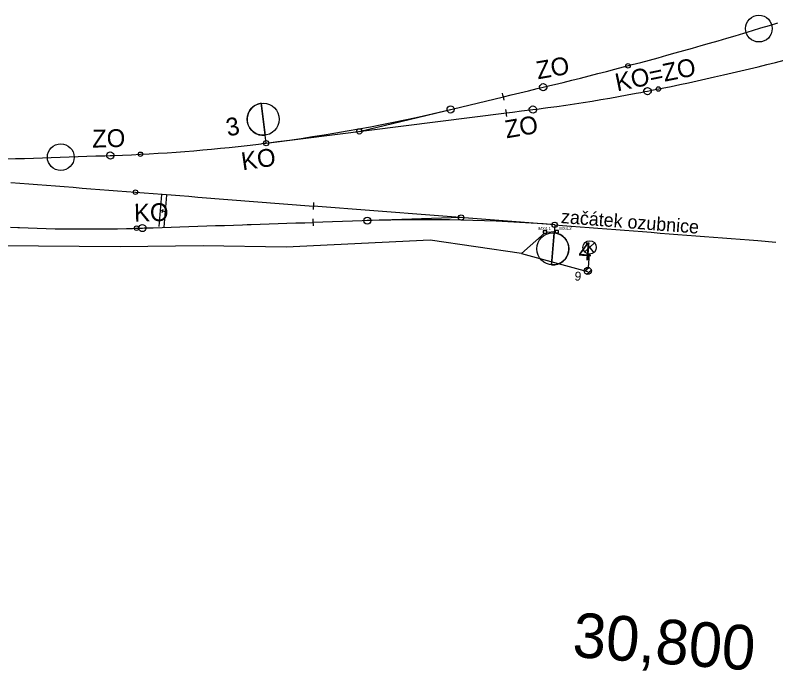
# Model space of a CAD drawing. Extents: x -669628 to -669207, y -977198 to -977075.
# Drawn here: x -669433.2 to -669347.9, y -977198.3 to -977124.9 of the extents above; entities that cross this region are included whole.
import ezdxf

# ---------------------------------------------------------------- set-up
doc = ezdxf.new("R2010")
doc.units = 0
for name, color, linetype in [('KOL_námezníky', 7, 'Continuous'), ('Navazující stavba', 7, 'Continuous'), ('SO 01-86-01', 7, 'Continuous'), ('SO 11-10-01', 7, 'Continuous')]:
    doc.layers.add(name, color=color, linetype=linetype)

# ---------------------------------------------------------------- blocks, each defined once
blk = doc.blocks.new('POINT_DISPLAY')
blk.add_line((0, 0), (0, 0))
blk = doc.blocks.new('Z3.50')
at = {"layer": 'KOL_námezníky'}
for p, q in [((-27.7, 181.3), (-26.5, -174.8)), ((33.2, -174.7), (31.9, 181.4))]:
    blk.add_line(p, q, dxfattribs=at)

msp = doc.modelspace()

# ---------------------------------------------------------------- linework, layer by layer
at = {"layer": 'Navazující stavba'}
msp.add_lwpolyline([(-669372.712, -977148.358), (-669371.856, -977148.424), (-669370.859, -977148.502), (-669369.862, -977148.579), (-669368.865, -977148.657), (-669367.868, -977148.735), (-669366.871, -977148.812), (-669365.874, -977148.89), (-669364.877, -977148.967), (-669363.88, -977149.045), (-669362.883, -977149.123), (-669361.886, -977149.2), (-669360.889, -977149.278), (-669359.892, -977149.355), (-669358.895, -977149.433), (-669357.898, -977149.511), (-669356.901, -977149.588), (-669355.905, -977149.666), (-669354.908, -977149.744), (-669353.911, -977149.821), (-669352.914, -977149.899), (-669351.917, -977149.976), (-669350.92, -977150.054), (-669349.923, -977150.132), (-669347.929, -977150.287)], dxfattribs=at)
at = {"layer": 'SO 01-86-01'}
for p, q in [((-669373.608, -977149.016), (-669373.987, -977149.016)), ((-669373.987, -977149.016), (-669373.987, -977149.292)), ((-669373.608, -977149.292), (-669373.608, -977149.016)), ((-669373.608, -977149.19), (-669372.647, -977149.113)), ((-669372.268, -977148.976), (-669372.647, -977148.976)), ((-669372.647, -977148.976), (-669372.647, -977149.251)), ((-669372.268, -977149.251), (-669372.268, -977148.976)), ((-669376.446, -977151.556), (-669373.862, -977149.292)), ((-669373.987, -977149.292), (-669373.608, -977149.292)), ((-669372.647, -977149.251), (-669372.268, -977149.251)), ((-669421.416, -977150.84), (-669436.037, -977150.686)), ((-669412.108, -977150.726), (-669421.416, -977150.84)), ((-669402.797, -977150.85), (-669412.108, -977150.726)), ((-669386.675, -977150.085), (-669402.797, -977150.85)), ((-669376.446, -977151.556), (-669386.675, -977150.085)), ((-669369.341, -977151.401), (-669368.256, -977150.369)), ((-669369.255, -977150.292), (-669368.343, -977151.479)), ((-669376.446, -977151.556), (-669369.045, -977153.593)), ((-669368.857, -977151.631), (-669368.973, -977153.127)), ((-669369.398, -977153.575), (-669368.894, -977153.144)), ((-669369.154, -977153.892), (-669368.617, -977153.432))]:
    msp.add_line(p, q, dxfattribs=at)
for centre, radius in [((-669368.799, -977150.885), 0.749), ((-669369.004, -977153.526), 0.4)]:
    msp.add_circle(centre, radius, dxfattribs=at)
at = {"layer": 'SO 11-10-01'}
for p, q in [((-669349.596, -977126.298), (-669348.639, -977126.006)), ((-669348.639, -977126.006), (-669347.684, -977125.712)), ((-669352.469, -977127.161), (-669351.511, -977126.876)), ((-669351.511, -977126.876), (-669350.553, -977126.588)), ((-669350.553, -977126.588), (-669349.596, -977126.298)), ((-669355.348, -977128.003), (-669354.388, -977127.725)), ((-669354.388, -977127.725), (-669353.428, -977127.444)), ((-669353.428, -977127.444), (-669352.469, -977127.161)), ((-669358.234, -977128.825), (-669357.271, -977128.553)), ((-669357.271, -977128.553), (-669356.31, -977128.279)), ((-669356.31, -977128.279), (-669355.348, -977128.003)), ((-669361.125, -977129.627), (-669360.616, -977129.487)), ((-669360.616, -977129.487), (-669360.16, -977129.362)), ((-669360.16, -977129.362), (-669359.197, -977129.095)), ((-669359.197, -977129.095), (-669358.234, -977128.825)), ((-669364.021, -977130.408), (-669363.055, -977130.15)), ((-669363.055, -977130.15), (-669362.089, -977129.889)), ((-669362.089, -977129.889), (-669361.125, -977129.627)), ((-669348.946, -977130.399), (-669347.976, -977130.156)), ((-669347.976, -977130.156), (-669347.007, -977129.909)), ((-669367.891, -977131.418), (-669366.923, -977131.169)), ((-669366.923, -977131.169), (-669365.955, -977130.918)), ((-669365.955, -977130.918), (-669364.988, -977130.664)), ((-669364.988, -977130.664), (-669364.021, -977130.408)), ((-669352.834, -977131.338), (-669351.861, -977131.109)), ((-669351.861, -977131.109), (-669350.888, -977130.876)), ((-669350.888, -977130.876), (-669349.916, -977130.639)), ((-669349.916, -977130.639), (-669348.946, -977130.399)), ((-669370.8, -977132.152), (-669369.83, -977131.91)), ((-669369.83, -977131.91), (-669368.86, -977131.665)), ((-669368.86, -977131.665), (-669367.891, -977131.418)), ((-669356.736, -977132.219), (-669355.759, -977132.004)), ((-669355.759, -977132.004), (-669354.783, -977131.786)), ((-669354.783, -977131.786), (-669353.808, -977131.564)), ((-669353.808, -977131.564), (-669352.834, -977131.338)), ((-669374.007, -977132.936), (-669373.714, -977132.866)), ((-669373.714, -977132.866), (-669373.254, -977132.754)), ((-669373.254, -977132.754), (-669372.742, -977132.63)), ((-669372.742, -977132.63), (-669371.771, -977132.392)), ((-669371.771, -977132.392), (-669370.8, -977132.152)), ((-669360.65, -977133.043), (-669359.67, -977132.842)), ((-669359.67, -977132.842), (-669358.691, -977132.638)), ((-669358.691, -977132.638), (-669357.713, -977132.43)), ((-669357.713, -977132.43), (-669356.736, -977132.219)), ((-669377.603, -977133.801), (-669376.631, -977133.567)), ((-669376.631, -977133.567), (-669375.659, -977133.333)), ((-669375.659, -977133.333), (-669374.686, -977133.099)), ((-669374.686, -977133.099), (-669374.007, -977132.936)), ((-669364.577, -977133.804), (-669363.594, -977133.621)), ((-669363.594, -977133.621), (-669363.064, -977133.52)), ((-669363.064, -977133.52), (-669362.611, -977133.433)), ((-669362.611, -977133.433), (-669362.308, -977133.373)), ((-669362.308, -977133.373), (-669361.63, -977133.239)), ((-669361.63, -977133.239), (-669360.65, -977133.043)), ((-669394.617, -977137.89), (-669378.462, -977134.007)), ((-669378.462, -977134.007), (-669377.603, -977133.801)), ((-669369.506, -977134.642), (-669368.518, -977134.485)), ((-669368.518, -977134.485), (-669367.531, -977134.323)), ((-669367.531, -977134.323), (-669366.546, -977134.155)), ((-669366.546, -977134.155), (-669365.561, -977133.982)), ((-669365.561, -977133.982), (-669364.577, -977133.804)), ((-669405.058, -977139.205), (-669405.62, -977134.74)), ((-669376.439, -977135.602), (-669375.447, -977135.477)), ((-669375.447, -977135.477), (-669375.158, -977135.44)), ((-669375.158, -977135.44), (-669374.455, -977135.351)), ((-669374.455, -977135.351), (-669373.999, -977135.291)), ((-669373.999, -977135.291), (-669373.464, -977135.219)), ((-669373.464, -977135.219), (-669372.473, -977135.083)), ((-669372.473, -977135.083), (-669371.483, -977134.941)), ((-669371.483, -977134.941), (-669370.494, -977134.794)), ((-669370.494, -977134.794), (-669369.506, -977134.642)), ((-669405.058, -977139.205), (-669378.132, -977135.815)), ((-669378.132, -977135.815), (-669377.432, -977135.727)), ((-669377.432, -977135.727), (-669376.439, -977135.602)), ((-669410.181, -977139.779), (-669409.186, -977139.679)), ((-669409.186, -977139.679), (-669408.192, -977139.573)), ((-669408.192, -977139.573), (-669407.198, -977139.462)), ((-669407.198, -977139.462), (-669406.205, -977139.346)), ((-669406.205, -977139.346), (-669405.619, -977139.275)), ((-669405.619, -977139.275), (-669405.5, -977139.26)), ((-669405.5, -977139.26), (-669405.212, -977139.224)), ((-669405.212, -977139.224), (-669405.058, -977139.205)), ((-669423.152, -977140.61), (-669422.527, -977140.589)), ((-669422.527, -977140.589), (-669422.153, -977140.577)), ((-669422.153, -977140.577), (-669421.153, -977140.539)), ((-669421.153, -977140.539), (-669420.154, -977140.496)), ((-669420.154, -977140.496), (-669419.155, -977140.448)), ((-669419.155, -977140.448), (-669418.157, -977140.395)), ((-669418.157, -977140.395), (-669417.159, -977140.336)), ((-669417.159, -977140.336), (-669416.161, -977140.272)), ((-669416.161, -977140.272), (-669415.163, -977140.203)), ((-669415.163, -977140.203), (-669414.166, -977140.129)), ((-669414.166, -977140.129), (-669413.169, -977140.049)), ((-669413.169, -977140.049), (-669412.173, -977139.965)), ((-669412.173, -977139.965), (-669411.177, -977139.875)), ((-669411.177, -977139.875), (-669410.181, -977139.779)), ((-669434.146, -977140.973), (-669433.147, -977140.94)), ((-669433.147, -977140.94), (-669432.147, -977140.907)), ((-669432.147, -977140.907), (-669431.148, -977140.874)), ((-669431.148, -977140.874), (-669430.148, -977140.841)), ((-669430.148, -977140.841), (-669429.149, -977140.808)), ((-669429.149, -977140.808), (-669428.149, -977140.775)), ((-669428.149, -977140.775), (-669427.15, -977140.742)), ((-669427.15, -977140.742), (-669426.15, -977140.709)), ((-669426.15, -977140.709), (-669425.151, -977140.676)), ((-669425.151, -977140.676), (-669424.152, -977140.643)), ((-669424.152, -977140.643), (-669423.152, -977140.61)), ((-669433.669, -977143.613), (-669432.672, -977143.69)), ((-669432.672, -977143.69), (-669431.675, -977143.768)), ((-669431.675, -977143.768), (-669430.678, -977143.845)), ((-669430.678, -977143.845), (-669429.681, -977143.923)), ((-669429.681, -977143.923), (-669428.684, -977144.001)), ((-669428.684, -977144.001), (-669427.687, -977144.078)), ((-669427.687, -977144.078), (-669426.69, -977144.156)), ((-669426.69, -977144.156), (-669425.693, -977144.233)), ((-669425.693, -977144.233), (-669424.696, -977144.311)), ((-669424.696, -977144.311), (-669423.699, -977144.389)), ((-669423.699, -977144.389), (-669422.702, -977144.466)), ((-669422.702, -977144.466), (-669421.705, -977144.544)), ((-669421.705, -977144.544), (-669420.708, -977144.622)), ((-669420.708, -977144.622), (-669419.711, -977144.699)), ((-669419.711, -977144.699), (-669418.715, -977144.777)), ((-669418.715, -977144.777), (-669417.718, -977144.854)), ((-669417.718, -977144.854), (-669416.721, -977144.932)), ((-669416.721, -977144.932), (-669415.724, -977145.01)), ((-669415.724, -977145.01), (-669414.727, -977145.087)), ((-669414.727, -977145.087), (-669413.73, -977145.165)), ((-669413.73, -977145.165), (-669412.733, -977145.242)), ((-669412.733, -977145.242), (-669399.768, -977146.251)), ((-669372.712, -977148.358), (-669399.768, -977146.252)), ((-669416.838, -977146.728), (-669416.459, -977146.859)), ((-669416.715, -977146.984), (-669416.586, -977146.603)), ((-669405.729, -977148.284), (-669404.73, -977148.251)), ((-669404.73, -977148.251), (-669403.73, -977148.218)), ((-669403.73, -977148.218), (-669402.731, -977148.185)), ((-669402.731, -977148.185), (-669401.731, -977148.152)), ((-669401.731, -977148.152), (-669400.732, -977148.119)), ((-669400.732, -977148.119), (-669399.809, -977148.089)), ((-669383.203, -977147.541), (-669399.809, -977148.089)), ((-669433.718, -977148.632), (-669432.879, -977148.667)), ((-669432.879, -977148.667), (-669432.719, -977148.674)), ((-669432.719, -977148.674), (-669431.72, -977148.711)), ((-669431.72, -977148.711), (-669430.72, -977148.743)), ((-669430.72, -977148.743), (-669429.721, -977148.769)), ((-669429.721, -977148.769), (-669428.721, -977148.79)), ((-669428.721, -977148.79), (-669427.721, -977148.806)), ((-669427.721, -977148.806), (-669426.721, -977148.817)), ((-669426.721, -977148.817), (-669425.721, -977148.822)), ((-669425.721, -977148.822), (-669424.721, -977148.822)), ((-669424.721, -977148.822), (-669423.721, -977148.817)), ((-669423.721, -977148.817), (-669422.721, -977148.807)), ((-669422.721, -977148.807), (-669421.721, -977148.791)), ((-669421.721, -977148.791), (-669420.721, -977148.77)), ((-669420.721, -977148.77), (-669420.031, -977148.753)), ((-669420.031, -977148.753), (-669419.722, -977148.744)), ((-669419.722, -977148.744), (-669418.934, -977148.72)), ((-669418.934, -977148.72), (-669418.722, -977148.713)), ((-669418.722, -977148.713), (-669417.723, -977148.68)), ((-669417.723, -977148.68), (-669416.723, -977148.647)), ((-669416.723, -977148.647), (-669415.724, -977148.614)), ((-669415.724, -977148.614), (-669414.724, -977148.581)), ((-669414.724, -977148.581), (-669413.725, -977148.548)), ((-669413.725, -977148.548), (-669412.725, -977148.515)), ((-669412.725, -977148.515), (-669411.726, -977148.482)), ((-669411.726, -977148.482), (-669410.727, -977148.449)), ((-669410.727, -977148.449), (-669409.727, -977148.416)), ((-669409.727, -977148.416), (-669408.728, -977148.383)), ((-669408.728, -977148.383), (-669407.728, -977148.35)), ((-669407.728, -977148.35), (-669407.187, -977148.332)), ((-669407.187, -977148.332), (-669406.729, -977148.317)), ((-669406.729, -977148.317), (-669405.729, -977148.284)), ((-669372.712, -977148.358), (-669373.061, -977152.844))]:
    msp.add_line(p, q, dxfattribs=at)
for points in [[(-669373.994, -977133.336), (-669374.128, -977133.314), (-669374.264, -977133.238), (-669374.346, -977133.161), (-669374.404, -977133.029), (-669374.409, -977132.869), (-669374.359, -977132.761), (-669374.283, -977132.652), (-669374.152, -977132.567), (-669374.02, -977132.536), (-669373.886, -977132.559), (-669373.75, -977132.634), (-669373.667, -977132.711), (-669373.61, -977132.843), (-669373.604, -977133.003), (-669373.654, -977133.111), (-669373.731, -977133.22), (-669373.861, -977133.305), (-669373.994, -977133.336)], [(-669362.295, -977133.773), (-669362.429, -977133.751), (-669362.565, -977133.675), (-669362.648, -977133.598), (-669362.705, -977133.466), (-669362.711, -977133.307), (-669362.661, -977133.198), (-669362.585, -977133.089), (-669362.454, -977133.005), (-669362.322, -977132.974), (-669362.187, -977132.996), (-669362.051, -977133.071), (-669361.969, -977133.149), (-669361.911, -977133.28), (-669361.906, -977133.44), (-669361.956, -977133.548), (-669362.032, -977133.658), (-669362.163, -977133.742), (-669362.295, -977133.773)], [(-669405.62, -977134.74), (-669405.17, -977138.312), (-669405.17, -977138.312)], [(-669375.145, -977135.84), (-669375.279, -977135.818), (-669375.415, -977135.742), (-669375.498, -977135.665), (-669375.555, -977135.534), (-669375.561, -977135.374), (-669375.511, -977135.265), (-669375.434, -977135.156), (-669375.304, -977135.072), (-669375.171, -977135.041), (-669375.037, -977135.063), (-669374.901, -977135.138), (-669374.819, -977135.216), (-669374.761, -977135.347), (-669374.756, -977135.507), (-669374.806, -977135.616), (-669374.882, -977135.725), (-669375.013, -977135.809), (-669375.145, -977135.84)], [(-669422.514, -977140.989), (-669422.648, -977140.967), (-669422.784, -977140.891), (-669422.867, -977140.814), (-669422.924, -977140.683), (-669422.93, -977140.523), (-669422.88, -977140.414), (-669422.803, -977140.305), (-669422.673, -977140.221), (-669422.54, -977140.19), (-669422.406, -977140.212), (-669422.27, -977140.288), (-669422.188, -977140.365), (-669422.13, -977140.496), (-669422.125, -977140.656), (-669422.175, -977140.765), (-669422.251, -977140.874), (-669422.382, -977140.958), (-669422.514, -977140.989)], [(-669418.92, -977149.119), (-669419.054, -977149.097), (-669419.19, -977149.021), (-669419.273, -977148.944), (-669419.331, -977148.813), (-669419.336, -977148.653), (-669419.286, -977148.544), (-669419.21, -977148.435), (-669419.079, -977148.351), (-669418.947, -977148.32), (-669418.813, -977148.342), (-669418.677, -977148.418), (-669418.594, -977148.495), (-669418.536, -977148.626), (-669418.531, -977148.786), (-669418.581, -977148.895), (-669418.657, -977149.004), (-669418.788, -977149.088), (-669418.92, -977149.119)], [(-669373.061, -977152.844), (-669372.782, -977149.255), (-669372.781, -977149.255)]]:
    msp.add_lwpolyline(points, dxfattribs=at)
for centre, radius in [((-669349.823, -977126.367), 1.5), ((-669364.491, -977130.533), 0.25), ((-669361.089, -977133.131), 0.25), ((-669405.395, -977136.526), 1.8), ((-669384.385, -977135.431), 0.4), ((-669394.617, -977137.89), 0.3), ((-669428.082, -977140.773), 1.5), ((-669405.058, -977139.205), 0.3), ((-669419.155, -977140.448), 0.25), ((-669419.711, -977144.699), 0.25), ((-669383.203, -977147.541), 0.3), ((-669393.721, -977147.888), 0.4), ((-669372.712, -977148.358), 0.3), ((-669419.592, -977148.74), 0.25), ((-669372.921, -977151.049), 1.8)]:
    msp.add_circle(centre, radius, dxfattribs=at)
for centre, radius, start, end in [((-669394.617, -977137.89), 16.616, 12.13647, 14.89521), ((-669405.395, -977136.526), 1.8, 97.17565, 277.1742), ((-669428.791, -976950.693), 190, 277.17565, 283.51568), ((-669394.617, -977137.89), 16.616, 5.79628, 8.55501), ((-669383.203, -977147.541), 16.616, 174.16989, 176.92862), ((-669383.203, -977147.541), 16.616, 180.51008, 183.26882), ((-669387.456, -977337.785), 190, 85.54926, 91.88929), ((-669372.921, -977151.049), 1.8, 265.54926, 85.54781)]:
    msp.add_arc(centre, radius, start, end, dxfattribs=at)

# ---------------------------------------------------------------- block references
at = {"layer": 'SO 01-86-01', "rotation": -4.450857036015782}
msp.add_blockref('POINT_DISPLAY', (-669369.004, -977153.526), dxfattribs=at)
at = {"layer": 'SO 11-10-01', "xscale": 0.010104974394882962, "yscale": 0.01010497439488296, "rotation": -5.081342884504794}
msp.add_blockref('Z3.50', (-669416.679, -977146.819), dxfattribs=at)
at = {"layer": 'SO 11-10-01'}
for p in [(-669387.5, -977147.206), (-669387.5, -977147.206), (-669393.721, -977147.888), (-669372.712, -977148.358), (-669372.712, -977148.358), (-669372.712, -977148.358), (-669372.712, -977148.358)]:
    msp.add_blockref('POINT_DISPLAY', p, dxfattribs=at)

# ---------------------------------------------------------------- texts
at = {"layer": 'Navazující stavba'}
msp.add_text('začátek ozubnice', height=1.5, rotation=355.5591, dxfattribs=at).set_placement((-669372.044, -977148.156))
at = {"layer": 'SO 01-86-01'}
for s, p in [('MX4.1', (-669374.532, -977148.945)), ('MX4.2', (-669372.211, -977148.936))]:
    msp.add_text(s, height=0.35, dxfattribs=at).set_placement(p)
msp.add_text('9', height=1, rotation=356.1, dxfattribs=at).set_placement((-669370.51, -977154.585))
at = {"layer": 'SO 11-10-01'}
for s, height, rotation, p in [('ZO', 2, 9.94353, (-669374.601, -977132.058)), ('KO=ZO', 2, 11.55415, (-669365.712, -977133.413)), ('3', 2, 10.08371, (-669409.372, -977138.454)), ('ZO', 2, 9.94353, (-669378.115, -977138.676)), ('ZO', 2, 1.3883, (-669424.541, -977139.709)), ('KO', 2, 8.27602, (-669407.698, -977142.258)), ('KO', 2, 1.4532, (-669419.843, -977148.012)), ('4', 2, 355.54636, (-669370.103, -977152.249)), ('30,800', 5, 355.63914, (-669370.819, -977196.769))]:
    msp.add_text(s, height=height, rotation=rotation, dxfattribs=at).set_placement(p)

doc.saveas('drawing.dxf')
